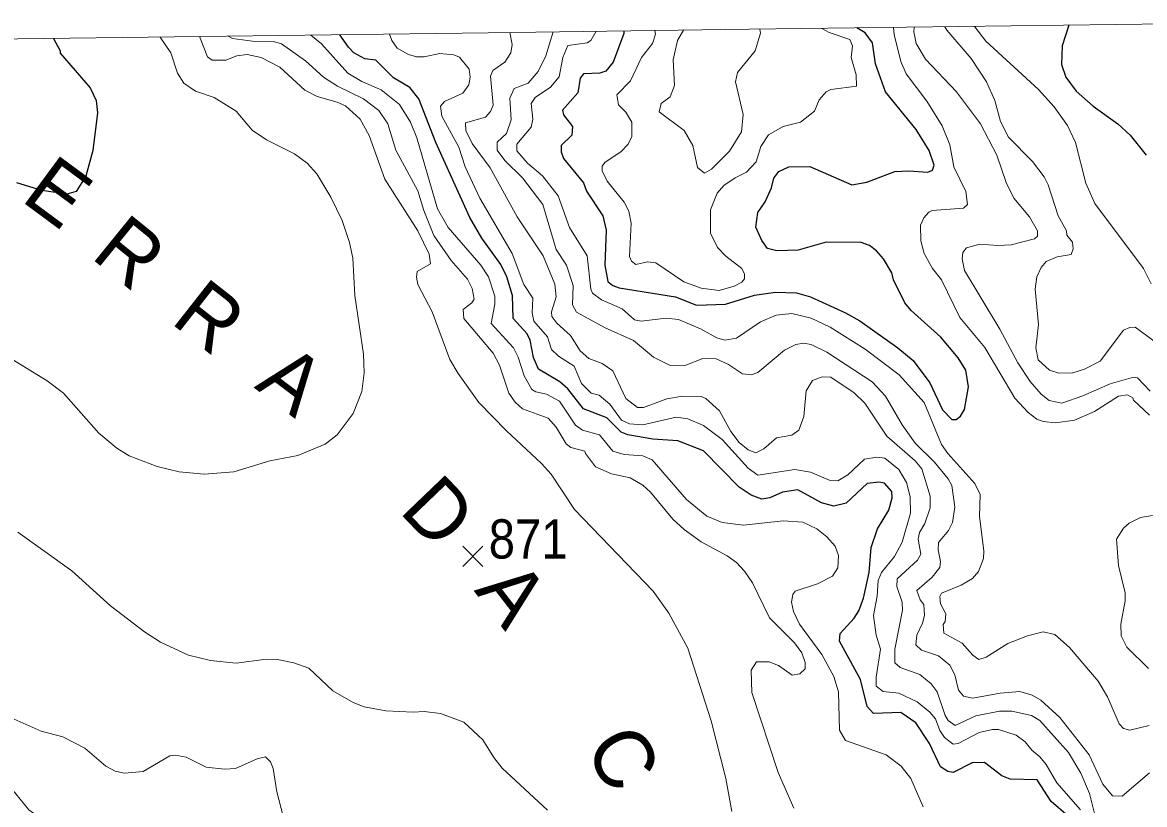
# Model space of a CAD drawing. Extents: x 265 to 291.4, y 7731.5 to 7759.6.
# Drawn here: x 272.004 to 274.292, y 7757.76 to 7759.355 of the extents above; entities that cross this region are included whole.
import ezdxf
from ezdxf.enums import TextEntityAlignment as Align

# ---------------------------------------------------------------- set-up
doc = ezdxf.new("R2010")
doc.units = 0
doc.header["$LTSCALE"] = 0.032
for name, color, linetype, lineweight in [('1', 7, 'Continuous', 25), ('2', 7, 'Continuous', 13), ('21', 7, 'Continuous', 25), ('61', 7, 'Continuous', 13), ('63', 7, 'Continuous', 25)]:
    doc.layers.add(name, color=color, linetype=linetype, lineweight=lineweight)

msp = doc.modelspace()

# ---------------------------------------------------------------- linework, layer by layer
at = {"layer": '1'}
for points in [[(273.2307, 7759.3376), (273.2301, 7759.3326), (273.2085, 7759.2739), (273.1934, 7759.2556), (273.1815, 7759.2516), (273.148, 7759.25), (273.1417, 7759.2412), (273.1369, 7759.2118), (273.1051, 7759.176), (273.1075, 7759.1665), (273.1258, 7759.1426), (273.1242, 7759.1251), (273.1027, 7759.1044), (273.1027, 7759.0909), (273.1074, 7759.0774), (273.148, 7759.0281), (273.1544, 7759.0113), (273.1878, 7758.9605), (273.1942, 7758.9318), (273.1918, 7758.8602), (273.1981, 7758.8268), (273.2077, 7758.8188), (273.2212, 7758.8141), (273.3358, 7758.7958), (273.3787, 7758.7783), (273.4376, 7758.7806), (273.4965, 7758.7989), (273.5394, 7758.8053), (273.5824, 7758.8037), (273.611, 7758.7958), (273.6826, 7758.7631), (273.7112, 7758.7464), (273.7892, 7758.6916), (273.8202, 7758.6661), (273.8544, 7758.62), (273.8799, 7758.5651), (273.899, 7758.5452), (273.9077, 7758.5452), (273.9165, 7758.5523), (273.9252, 7758.5659), (273.9332, 7758.612), (273.9276, 7758.6462), (273.9117, 7758.6709), (273.8767, 7758.7131), (273.8162, 7758.7679), (273.8035, 7758.7831), (273.7804, 7758.83), (273.7765, 7758.8443), (273.7597, 7758.8729), (273.7454, 7758.8896), (273.7311, 7758.9), (273.7144, 7758.9063), (273.6428, 7758.9071), (273.5856, 7758.8904), (273.5426, 7758.8896), (273.5235, 7758.8944), (273.5116, 7758.9103), (273.4996, 7758.9374), (273.5036, 7758.9676), (273.5187, 7758.9891), (273.5314, 7759.0177), (273.5362, 7759.0376), (273.5466, 7759.0511), (273.5665, 7759.0607), (273.6094, 7759.0615), (273.6953, 7759.0241), (273.7256, 7759.0296), (273.7828, 7759.0511), (273.8115, 7759.0527), (273.8504, 7759.0495), (273.86, 7759.0535), (273.8632, 7759.0639), (273.8528, 7759.0941), (273.8266, 7759.137), (273.7637, 7759.2134), (273.7438, 7759.2707), (273.7375, 7759.3136), (273.7224, 7759.3335), (273.7057, 7759.3438)], [(274.1376, 7759.3495), (274.1241, 7759.3073), (274.1225, 7759.2691), (274.1312, 7759.2436), (274.1527, 7759.215), (274.1869, 7759.184), (274.2378, 7759.1482), (274.2625, 7759.1251), (274.2951, 7759.0845)], [(272.0677, 7759.3223), (272.0813, 7759.2969), (272.0813, 7759.2921), (272.1425, 7759.2214), (272.1545, 7759.1959), (272.1576, 7759.1705), (272.1481, 7759.0941), (272.1338, 7759.0416), (272.1139, 7759.0106), (272.0948, 7759.005), (272.0439, 7759.0121), (271.993, 7759.028)], [(274.136, 7757.737), (274.1018, 7757.7664), (274.0732, 7757.811), (274.0183, 7757.8125), (274.0008, 7757.8189), (273.9658, 7757.846), (273.9403, 7757.8452), (273.9021, 7757.8261), (273.891, 7757.8277), (273.8759, 7757.8372), (273.8536, 7757.885), (273.8258, 7757.9271), (273.7948, 7757.9478), (273.7391, 7757.9462), (273.7263, 7757.9605), (273.7128, 7758.0154), (273.6699, 7758.0934), (273.6715, 7758.1093), (273.7001, 7758.1403), (273.7096, 7758.1554), (273.7192, 7758.1809), (273.7303, 7758.2334), (273.7343, 7758.2843), (273.7478, 7758.3225), (273.7709, 7758.3607), (273.7773, 7758.3861), (273.7765, 7758.3988), (273.7621, 7758.4155), (273.7502, 7758.4179), (273.7263, 7758.4147), (273.6834, 7758.3749), (273.6587, 7758.3686), (273.6333, 7758.3757), (273.5848, 7758.402), (273.5537, 7758.3972), (273.5283, 7758.3861), (273.5116, 7758.3829), (273.4901, 7758.3909), (273.4654, 7758.4076), (273.393, 7758.4816), (273.3406, 7758.5022), (273.2896, 7758.5054), (273.2387, 7758.5142), (273.2252, 7758.5197), (273.1958, 7758.5492), (273.148, 7758.5675), (273.1162, 7758.608), (273.1003, 7758.6224), (273.0566, 7758.6478), (273.0462, 7758.6717), (273.0398, 7758.7075), (273.0335, 7758.7202), (273.0048, 7758.7512), (273.0033, 7758.7982), (272.9921, 7758.8364), (272.9794, 7758.8618), (272.9412, 7758.9151), (272.9165, 7758.9573), (272.8473, 7759.11), (272.8123, 7759.1991), (272.794, 7759.2222), (272.7606, 7759.242), (272.7248, 7759.2778), (272.7026, 7759.281), (272.6803, 7759.2929), (272.6691, 7759.3049), (272.6515, 7759.33)]]:
    msp.add_lwpolyline(points, dxfattribs=at)
at = {"layer": '2'}
for points in [[(272.907, 7759.0607), (272.8943, 7759.1005), (272.8593, 7759.1641), (272.8569, 7759.184), (272.8648, 7759.1935), (272.9022, 7759.211), (272.9142, 7759.2277), (272.9173, 7759.2436), (272.915, 7759.2596), (272.8951, 7759.2842), (272.8839, 7759.289), (272.8553, 7759.2914), (272.8235, 7759.285), (272.8076, 7759.285), (272.7917, 7759.2898), (272.7686, 7759.3025), (272.7575, 7759.3184), (272.7526, 7759.3313)], [(272.9983, 7759.3346), (273.0025, 7759.3097), (273.0001, 7759.293), (272.9881, 7759.2739), (272.9635, 7759.2572), (272.9587, 7759.2452), (272.9643, 7759.1864), (272.9587, 7759.1736), (272.9484, 7759.1617), (272.9078, 7759.1506), (272.9086, 7759.1347), (272.9213, 7759.1084), (272.9579, 7759.0583), (273.0128, 7758.9589), (273.0661, 7758.8793), (273.09, 7758.8212), (273.0924, 7758.7958), (273.0828, 7758.7648), (273.0836, 7758.7552), (273.0939, 7758.7417), (273.1218, 7758.717), (273.1417, 7758.6852), (273.1592, 7758.6701), (273.1862, 7758.6597), (273.2077, 7758.6446), (273.2347, 7758.5882), (273.2586, 7758.5699), (273.2706, 7758.5699), (273.3183, 7758.5874), (273.3501, 7758.5929), (273.3883, 7758.5921), (273.3978, 7758.5882), (273.4257, 7758.5635), (273.4487, 7758.5213), (273.4654, 7758.4983), (273.4837, 7758.4839), (273.4997, 7758.4776), (273.5156, 7758.4855), (273.5418, 7758.5078), (273.5728, 7758.5134), (273.5871, 7758.5237), (273.5975, 7758.5516), (273.6023, 7758.6041), (273.615, 7758.6248), (273.6349, 7758.6327), (273.6524, 7758.6319), (273.7001, 7758.6001), (273.7216, 7758.5786), (273.7669, 7758.5118), (273.8242, 7758.4609), (273.8377, 7758.445), (273.8552, 7758.3893), (273.8552, 7758.3654), (273.8441, 7758.3336), (273.8329, 7758.3153), (273.8306, 7758.3018), (273.8361, 7758.2708), (273.829, 7758.2588), (273.7876, 7758.2206), (273.7868, 7758.2047), (273.7979, 7758.1729), (273.7987, 7758.157), (273.7828, 7758.0775), (273.7828, 7758.0496), (273.794, 7758.0401), (273.8338, 7758.0257), (273.8568, 7758.0067), (273.8695, 7757.99), (273.8854, 7757.9422), (273.8918, 7757.9319), (273.9061, 7757.9215), (273.9483, 7757.9414), (273.996, 7757.951), (274.0215, 7757.951), (274.0613, 7757.9422), (274.0788, 7757.9319), (274.1368, 7757.8667), (274.1623, 7757.8245), (274.1798, 7757.7831), (274.1957, 7757.7179)], [(273.0861, 7759.3357), (273.0715, 7759.2869), (273.0558, 7759.2548), (273.0351, 7759.2309), (273.0072, 7759.2206), (272.9977, 7759.2007), (273.0009, 7759.1561), (272.9913, 7759.1283), (272.9722, 7759.1108), (272.9722, 7759.0949), (272.9881, 7759.0734), (273.024, 7759.0384), (273.0653, 7758.9835), (273.0924, 7758.892), (273.1138, 7758.8602), (273.1274, 7758.8189), (273.1258, 7758.7791), (273.1337, 7758.764), (273.1926, 7758.7321), (273.2499, 7758.7067), (273.2912, 7758.6725), (273.3246, 7758.6558), (273.3565, 7758.6566), (273.3915, 7758.6701), (273.4185, 7758.6693), (273.444, 7758.6574), (273.4726, 7758.6383), (273.4901, 7758.6367), (273.5036, 7758.6415), (273.5577, 7758.6868), (273.5808, 7758.6987), (273.5967, 7758.7011), (273.6126, 7758.6987), (273.6444, 7758.6828), (273.7367, 7758.6224), (273.7637, 7758.5929), (273.7979, 7758.5349), (273.8242, 7758.4975), (273.864, 7758.4585), (273.8918, 7758.4243), (273.899, 7758.4108), (273.9053, 7758.367), (273.9006, 7758.3352), (273.8926, 7758.3193), (273.8719, 7758.2946), (273.8711, 7758.2795), (273.8759, 7758.2557), (273.8743, 7758.2437), (273.8592, 7758.2238), (273.8274, 7758.1968), (273.8345, 7758.1777), (273.8417, 7758.1681), (273.8433, 7758.1459), (273.8393, 7758.13), (273.8274, 7758.1061), (273.8258, 7758.0862), (273.8369, 7758.0751), (273.8719, 7758.0639), (273.895, 7758.0448), (273.9053, 7758.025), (273.9125, 7757.9939), (273.9228, 7757.9812), (273.9419, 7757.9772), (273.9976, 7757.9876), (274.0374, 7757.9907), (274.0629, 7757.9836), (274.0804, 7757.9732), (274.1193, 7757.9382), (274.179, 7757.8619), (274.2068, 7757.8022), (274.2267, 7757.7784), (274.2466, 7757.7776), (274.3023, 7757.8253)], [(273.9411, 7758.2214), (273.9531, 7758.2358), (273.9634, 7758.262), (273.9642, 7758.2779), (273.9554, 7758.3479), (273.957, 7758.3925), (273.9459, 7758.4147), (273.891, 7758.476), (273.8783, 7758.4943), (273.8425, 7758.5802), (273.7916, 7758.6367), (273.7224, 7758.6892), (273.6508, 7758.7337), (273.6126, 7758.752), (273.5728, 7758.7616), (273.541, 7758.7584), (273.5092, 7758.7449), (273.4599, 7758.7115), (273.436, 7758.7075), (273.4201, 7758.7123), (273.3867, 7758.7305), (273.3421, 7758.7496), (273.3167, 7758.752), (273.2658, 7758.7457), (273.2523, 7758.7488), (273.2268, 7758.7711), (273.1846, 7758.7894), (273.1663, 7758.8029), (273.1631, 7758.8109), (273.156, 7758.8793), (273.1194, 7758.9366), (273.0963, 7759.0018), (273.0645, 7759.0424), (273.0343, 7759.0678), (273.012, 7759.0933), (273.012, 7759.1068), (273.0414, 7759.1418), (273.0446, 7759.1577), (273.0414, 7759.1896), (273.0494, 7759.2023), (273.0812, 7759.223), (273.0987, 7759.2444), (273.1059, 7759.2834), (273.1162, 7759.3081), (273.156, 7759.3136), (273.1632, 7759.3184), (273.1735, 7759.3359), (273.1739, 7759.3369)], [(273.2938, 7759.3384), (273.2953, 7759.3313), (273.2888, 7759.3121), (273.2666, 7759.2834), (273.2443, 7759.2357), (273.2164, 7759.2071), (273.2196, 7759.1872), (273.2347, 7759.172), (273.2467, 7759.1514), (273.2467, 7759.1227), (273.2395, 7759.1068), (273.2252, 7759.0917), (273.1918, 7759.0694), (273.1862, 7759.0623), (273.1862, 7759.0527), (273.1966, 7759.0312), (273.2308, 7758.9883), (273.2403, 7758.97), (273.2451, 7758.9461), (273.2419, 7758.8777), (273.2459, 7758.8682), (273.2546, 7758.8618), (273.2785, 7758.8666), (273.296, 7758.865), (273.3525, 7758.826), (273.3883, 7758.8133), (273.4249, 7758.8085), (273.4551, 7758.8173), (273.471, 7758.8252), (273.4766, 7758.8324), (273.4766, 7758.8419), (273.471, 7758.8531), (273.4384, 7758.8785), (273.4217, 7758.896), (273.4074, 7758.9255), (273.4074, 7758.9732), (273.4209, 7759.0066), (273.4344, 7759.0225), (273.4575, 7759.0384), (273.4806, 7759.0495), (273.5004, 7759.071), (273.51, 7759.102), (273.5251, 7759.1259), (273.5553, 7759.1426), (273.5903, 7759.1514), (273.619, 7759.1744), (273.6285, 7759.1975), (273.6428, 7759.2134), (273.6524, 7759.2182), (273.7049, 7759.2253), (273.7041, 7759.2484), (273.6937, 7759.2834), (273.6969, 7759.3073), (273.6913, 7759.32), (273.6492, 7759.3343), (273.6343, 7759.3429)], [(273.508, 7759.3412), (273.5089, 7759.3334), (273.4981, 7759.2969), (273.4622, 7759.2532), (273.4583, 7759.2341), (273.4734, 7759.1673), (273.4702, 7759.1323), (273.4455, 7759.0925), (273.4089, 7759.0559), (273.3946, 7759.0479), (273.3803, 7759.0591), (273.3708, 7759.1044), (273.3533, 7759.1347), (273.3024, 7759.1728), (273.3063, 7759.1896), (273.3246, 7759.2031), (273.3334, 7759.2261), (273.331, 7759.2786), (273.3397, 7759.3184), (273.3518, 7759.3392)], [(273.7803, 7759.3448), (273.7812, 7759.3303), (273.7948, 7759.2755), (273.8059, 7759.25), (273.8481, 7759.1943), (273.8791, 7759.1442), (273.895, 7759.1052), (273.9029, 7759.0607), (273.9276, 7759.0106), (273.9308, 7758.9835), (273.9228, 7758.9764), (273.8592, 7758.9716), (273.852, 7758.9684), (273.8417, 7758.9565), (273.8353, 7758.9414), (273.8361, 7758.9095), (273.8425, 7758.8841), (273.86, 7758.8531), (273.8783, 7758.83), (273.9157, 7758.7536), (273.9666, 7758.6924), (274.0278, 7758.589), (274.0549, 7758.5595), (274.0724, 7758.546), (274.0851, 7758.5412), (274.1106, 7758.5388), (274.1488, 7758.5444), (274.1901, 7758.5619), (274.2387, 7758.5929), (274.257, 7758.5961), (274.2681, 7758.5897), (274.2697, 7758.585), (274.3023, 7758.554)], [(274.3031, 7758.6033), (274.2776, 7758.6303), (274.2697, 7758.6319), (274.222, 7758.6184), (274.1663, 7758.5937), (274.1233, 7758.5786), (274.0978, 7758.5842), (274.0811, 7758.5969), (274.0589, 7758.6232), (274.0334, 7758.6613), (273.9968, 7758.7298), (273.9252, 7758.8491), (273.9204, 7758.8729), (273.9212, 7758.8857), (273.9292, 7758.8952), (273.9563, 7758.9032), (273.9929, 7758.9), (274.0199, 7758.9016), (274.0676, 7758.9135), (274.074, 7758.9191), (274.074, 7758.9302), (274.0573, 7758.9589), (274.0255, 7758.997), (274.0095, 7759.0289), (273.9905, 7759.0845), (273.9578, 7759.1482), (273.9085, 7759.2134), (273.8457, 7759.2802), (273.8266, 7759.3121), (273.8218, 7759.3359), (273.8225, 7759.3454)], [(274.0875, 7759.04), (274.0636, 7759.0718), (274.0143, 7759.1211), (273.9984, 7759.153), (273.9865, 7759.1959), (273.9698, 7759.2341), (273.9387, 7759.2818), (273.8886, 7759.3391), (273.8849, 7759.3462)], [(273.9451, 7759.347), (273.9458, 7759.3458), (273.9682, 7759.3168), (274.0756, 7759.2182), (274.1074, 7759.1832), (274.1352, 7759.145), (274.1511, 7759.11), (274.172, 7759.0272), (274.1909, 7758.9859), (274.2896, 7758.8531), (274.3055, 7758.822)], [(272.285, 7759.3252), (272.3072, 7759.293), (272.3207, 7759.2516), (272.3335, 7759.2309), (272.3573, 7759.215), (272.3955, 7759.2023), (272.4401, 7759.1744), (272.4727, 7759.1354), (272.5021, 7759.1156), (272.5594, 7759.0869), (272.5848, 7759.0678), (272.6047, 7759.0464), (272.6334, 7758.9986), (272.6564, 7758.9509), (272.6715, 7758.9064), (272.6779, 7758.8745), (272.6819, 7758.7982), (272.6994, 7758.6789), (272.701, 7758.6407), (272.6962, 7758.6025), (272.6787, 7758.5579), (272.6461, 7758.5142), (272.6214, 7758.4951), (272.5658, 7758.472), (272.5085, 7758.4609), (272.4353, 7758.4386), (272.3748, 7758.4338), (272.3239, 7758.4386), (272.2794, 7758.4497), (272.2221, 7758.4712), (272.1966, 7758.4871), (272.1601, 7758.5174), (272.0885, 7758.5993), (272.055, 7758.624), (271.9437, 7758.6924)], [(273.4503, 7757.7465), (273.4384, 7757.8134), (273.4082, 7757.9311), (273.3612, 7758.0791), (273.3222, 7758.1506), (273.2904, 7758.1952), (273.1297, 7758.3622), (273.082, 7758.4338), (273.0629, 7758.4561), (272.9913, 7758.5221), (272.9348, 7758.5802), (272.8927, 7758.6391), (272.876, 7758.6677), (272.8394, 7758.7648), (272.8108, 7758.8204), (272.8076, 7758.8355), (272.8092, 7758.8475), (272.8362, 7758.8626), (272.8338, 7758.8825), (272.8107, 7758.9302), (272.7431, 7759.0352), (272.7113, 7759.1243), (272.693, 7759.1577), (272.6628, 7759.1848), (272.6461, 7759.1927), (272.6055, 7759.2039), (272.5801, 7759.2166), (272.5292, 7759.2635), (272.491, 7759.2834), (272.4623, 7759.2898), (272.4417, 7759.2866), (272.4194, 7759.2778), (272.3915, 7759.2778), (272.382, 7759.285), (272.3657, 7759.3262)], [(272.4241, 7759.327), (272.4325, 7759.322), (272.4735, 7759.3168), (272.5164, 7759.316), (272.5323, 7759.3112), (272.5817, 7759.277), (272.6182, 7759.2436), (272.6469, 7759.2253), (272.6994, 7759.1991), (272.7312, 7759.1752), (272.7495, 7759.1482), (272.7654, 7759.0949), (272.8108, 7759.0114), (272.8227, 7758.9716), (272.8434, 7758.9207), (272.8784, 7758.8698), (272.9118, 7758.8316), (272.9213, 7758.8125), (272.9253, 7758.791), (272.9205, 7758.7831), (272.903, 7758.7695), (272.9046, 7758.7512), (272.9643, 7758.6804), (272.977, 7758.6566), (272.9961, 7758.5993), (273.0088, 7758.581), (273.0239, 7758.5675), (273.0764, 7758.5484), (273.0924, 7758.5301), (273.113, 7758.4959), (273.1226, 7758.4887), (273.1512, 7758.4808), (273.152, 7758.476), (273.1727, 7758.449), (273.2053, 7758.4346), (273.2435, 7758.4267), (273.269, 7758.4115), (273.2849, 7758.3972), (273.3302, 7758.3424), (273.3533, 7758.3209), (273.3883, 7758.2962), (273.4408, 7758.2676), (273.4599, 7758.254), (273.4766, 7758.2366), (273.4925, 7758.2127), (273.5275, 7758.1411), (273.5784, 7758.0902), (273.5935, 7758.0695), (273.5999, 7758.0504), (273.5999, 7758.0369), (273.5895, 7758.0273), (273.5736, 7758.0242), (273.5454, 7758.0441), (273.5267, 7758.0512), (273.5012, 7758.0512), (273.4901, 7758.0345), (273.4917, 7757.9892), (273.545, 7757.8261), (273.5768, 7757.7529)], [(272.6962, 7759.2349), (272.6676, 7759.2516), (272.6143, 7759.3113), (272.5927, 7759.3292)], [(272.872, 7758.9366), (272.8505, 7758.9748), (272.8084, 7759.1195), (272.7956, 7759.1514), (272.7734, 7759.188), (272.736, 7759.2174), (272.6962, 7759.2349)], [(273.047, 7758.7457), (273.0438, 7758.7632), (273.0446, 7758.7926), (273.0263, 7758.8204), (273.0025, 7758.8841), (272.9372, 7758.997), (272.907, 7759.0607)], [(274.1464, 7758.8936), (274.1448, 7758.9071), (274.1336, 7758.9215), (274.1328, 7758.9302), (274.1161, 7758.9605), (274.0955, 7759.0241), (274.0875, 7759.04)], [(273.8409, 7757.7561), (273.8154, 7757.8134), (273.7956, 7757.8388), (273.7653, 7757.8619), (273.6826, 7757.8913), (273.6699, 7757.912), (273.6683, 7757.99), (273.6587, 7758.0218), (273.6341, 7758.0663), (273.5887, 7758.1284), (273.576, 7758.1538), (273.572, 7758.1729), (273.5752, 7758.1888), (273.58, 7758.1952), (273.6253, 7758.2103), (273.6556, 7758.2262), (273.6667, 7758.2429), (273.6683, 7758.2684), (273.6611, 7758.2875), (273.6444, 7758.3066), (273.6237, 7758.3225), (273.5951, 7758.336), (273.5553, 7758.3392), (273.4742, 7758.3304), (273.4312, 7758.3352), (273.3994, 7758.3487), (273.3581, 7758.3821), (273.288, 7758.4633), (273.269, 7758.4712), (273.2308, 7758.4744), (273.2077, 7758.4808), (273.1807, 7758.5142), (273.1465, 7758.5237), (273.1321, 7758.5341), (273.0995, 7758.5826), (273.0725, 7758.5969), (273.051, 7758.6017), (273.043, 7758.6064), (273.0271, 7758.6343), (273.0152, 7758.6725), (273.0056, 7758.6916), (272.9603, 7758.7409), (272.9675, 7758.7807), (272.9675, 7758.7966), (272.9547, 7758.8364), (272.9388, 7758.8602), (272.872, 7758.9366)], [(274.3118, 7758.7051), (274.2729, 7758.7337), (274.2617, 7758.7329), (274.249, 7758.7274), (274.2013, 7758.6645), (274.1694, 7758.6478), (274.1456, 7758.6407), (274.1169, 7758.6399), (274.0979, 7758.6462), (274.0748, 7758.6669), (274.07, 7758.6916), (274.0756, 7758.7393), (274.0692, 7758.8109), (274.0724, 7758.8364), (274.0811, 7758.8554), (274.0915, 7758.8674), (274.1138, 7758.8769), (274.1424, 7758.8817), (274.1464, 7758.8936)], [(274.1615, 7757.7497), (274.113, 7757.8046), (274.0915, 7757.842), (274.0787, 7757.8579), (274.062, 7757.8714), (274.0485, 7757.8881), (274.0302, 7757.9016), (273.9944, 7757.9136), (273.9817, 7757.9136), (273.9547, 7757.9072), (273.9117, 7757.8849), (273.9021, 7757.8833), (273.8839, 7757.8969), (273.8743, 7757.9112), (273.8656, 7757.9351), (273.8544, 7757.9486), (273.8282, 7757.9701), (273.7908, 7757.9876), (273.759, 7757.9907), (273.7447, 7758.0019), (273.7447, 7758.0202), (273.7534, 7758.0775), (273.7447, 7758.1061), (273.7391, 7758.1459), (273.747, 7758.1856), (273.7486, 7758.2175), (273.7558, 7758.2334), (273.782, 7758.266), (273.7979, 7758.2954), (273.8147, 7758.3543), (273.8139, 7758.3877), (273.8067, 7758.4171), (273.7908, 7758.4434), (273.7622, 7758.4664), (273.7463, 7758.4688), (273.7208, 7758.4649), (273.6874, 7758.433), (273.6667, 7758.4203), (273.6508, 7758.4211), (273.611, 7758.4378), (273.5792, 7758.4434), (273.5036, 7758.4322), (273.4837, 7758.4466), (273.4312, 7758.5046), (273.3931, 7758.5333), (273.3612, 7758.5468), (273.3374, 7758.55), (273.269, 7758.5349), (273.2419, 7758.5364), (273.226, 7758.5444), (273.2021, 7758.577), (273.1799, 7758.5953), (273.1639, 7758.5993), (273.144, 7758.6192), (273.129, 7758.6542), (273.0971, 7758.6749), (273.0828, 7758.6884), (273.0749, 7758.7139), (273.047, 7758.7457)], [(274.3079, 7758.3495), (274.284, 7758.3455), (274.2609, 7758.3344), (274.249, 7758.324), (274.2347, 7758.3018), (274.2386, 7758.2477), (274.2522, 7758.192), (274.2522, 7758.1761), (274.2434, 7758.1284), (274.2442, 7758.1045), (274.2561, 7758.0814), (274.2999, 7758.0377)], [(271.9954, 7758.3161), (272.1052, 7758.2373), (272.1839, 7758.1658), (272.2531, 7758.1125), (272.2857, 7758.0918), (272.343, 7758.0647), (272.3876, 7758.0544), (272.4401, 7758.0488), (272.5021, 7758.0568), (272.5244, 7758.056), (272.5578, 7758.0496), (272.588, 7758.0385), (272.6373, 7757.9923), (272.6787, 7757.9685), (272.701, 7757.9597), (272.7455, 7757.9518), (272.8012, 7757.9486), (272.8235, 7757.9502), (272.8569, 7757.9462), (272.9046, 7757.9287), (272.9428, 7757.8921), (272.9651, 7757.8563), (272.9826, 7757.8348), (273.0749, 7757.7489)], [(273.8854, 7758.1339), (273.887, 7758.1491), (273.8759, 7758.1697), (273.8743, 7758.1848), (273.8783, 7758.1912), (273.9181, 7758.2079), (273.9411, 7758.2214)], [(274.3015, 7757.9215), (274.2617, 7757.912), (274.249, 7757.9152), (274.2402, 7757.9247), (274.2164, 7757.9804), (274.1973, 7758.0122), (274.1392, 7758.0806), (274.109, 7758.1069), (274.0851, 7758.1124), (274.0533, 7758.1045), (274.0135, 7758.0886), (273.969, 7758.0607), (273.9539, 7758.056), (273.9419, 7758.0647), (273.9204, 7758.0894), (273.8831, 7758.1101), (273.8815, 7758.1276), (273.8854, 7758.1339)], [(272.5363, 7757.737), (272.5228, 7757.7863), (272.5156, 7757.834), (272.51, 7757.8475), (272.4997, 7757.8579), (272.483, 7757.8539), (272.4385, 7757.834), (272.4162, 7757.8324), (272.3788, 7757.8364), (272.3382, 7757.8571), (272.316, 7757.8611), (272.3048, 7757.8595), (272.2507, 7757.8277), (272.2126, 7757.8245), (272.1935, 7757.8285), (272.1744, 7757.8388), (272.1314, 7757.8754), (272.0869, 7757.8985), (272.0423, 7757.9104), (271.9874, 7757.9343)], [(271.9643, 7757.815), (272.0177, 7757.7497), (272.0487, 7757.7274), (272.1489, 7757.6662), (272.2006, 7757.6081), (272.2269, 7757.5866), (272.2491, 7757.5739), (272.281, 7757.5612)]]:
    msp.add_lwpolyline(points, dxfattribs=at)
at = {"layer": '21'}
for p, q in [((272.902, 7758.287), (272.9432, 7758.2458)), ((272.9432, 7758.287), (272.902, 7758.2458))]:
    msp.add_line(p, q, dxfattribs=at)
at = {"layer": '63', "lineweight": 13}
msp.add_lwpolyline([(274.5533, 7759.355), (274.0201, 7759.348), (273.4869, 7759.341), (272.9538, 7759.334), (272.4206, 7759.327), (271.8874, 7759.32), (271.3543, 7759.3129), (270.8211, 7759.3059), (270.2879, 7759.2988), (269.7547, 7759.2917), (269.2216, 7759.2846), (268.6884, 7759.2775), (268.1552, 7759.2703), (267.622, 7759.2632), (267.0888, 7759.256), (266.5557, 7759.2488), (266.0225, 7759.2416), (265.4893, 7759.2344), (264.9561, 7759.2271)], dxfattribs=at)

# ---------------------------------------------------------------- texts
at = {"layer": '61'}
for s, rotation, p in [('E', 323.529, (272.042, 7758.9611)), ('R', 320.918, (272.1865, 7758.84)), ('R', 321.855, (272.3497, 7758.708)), ('A', 322.914, (272.518, 7758.5787)), ('D', 313.835, (272.8103, 7758.3162)), ('A', 307.639, (272.9566, 7758.1543)), ('C', 300.046, (273.1774, 7757.8257))]:
    msp.add_text(s, height=0.12, rotation=rotation, dxfattribs=at).set_placement(p, align=Align.CENTER)
at = {"layer": '61', "width": 0.9}
msp.add_text('871', height=0.08, dxfattribs=at).set_placement((273.0353, 7758.262), align=Align.CENTER)

doc.saveas('drawing.dxf')
